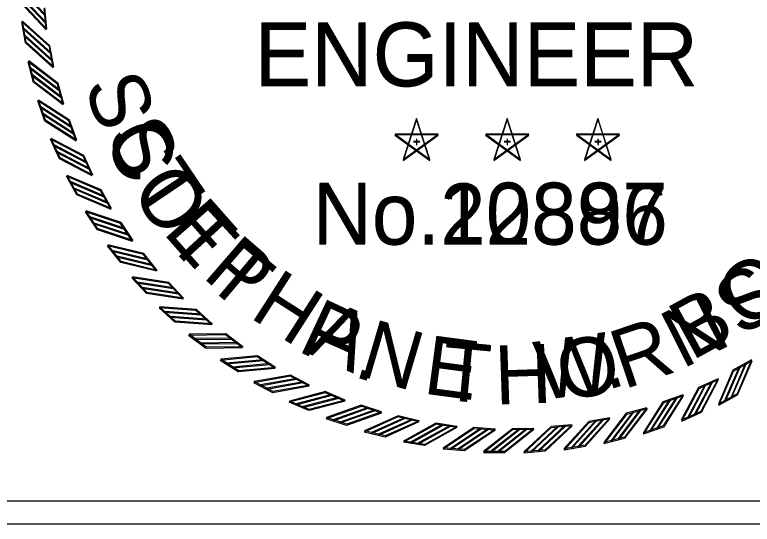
# Model space of a CAD drawing. Extents: x 0 to 1228740, y 0 to 152440.
# Drawn here: x 30.798 to 32.682, y 17.345 to 18.648 of the extents above; entities that cross this region are included whole.
import ezdxf

# ---------------------------------------------------------------- set-up
doc = ezdxf.new("R2010")
doc.units = 0
for name, color, linetype in [('R_No Plot', 7, 'Continuous'), ('STAMP', 7, 'Continuous'), ('STAMP_SWB', 7, 'Continuous')]:
    doc.layers.add(name, color=color, linetype=linetype)

msp = doc.modelspace()

# ---------------------------------------------------------------- linework, layer by layer
at = {"layer": 'R_No Plot'}
msp.add_lwpolyline([(30.6265, 20.205), (33.4865, 20.205), (33.4865, 17.3449), (30.6265, 17.3449)], close=True, dxfattribs=at)
msp.add_lwpolyline([(30.6265, 20.205), (33.4865, 20.205), (33.4865, 17.3449), (30.6265, 17.3449)], close=True, dxfattribs=at)
msp.add_lwpolyline([(30.6665, 20.1432), (30.6665, 17.4052), (33.4231, 17.4052)], dxfattribs=at)
msp.add_lwpolyline([(30.6665, 20.1432), (30.6665, 17.4052), (33.4231, 17.4052)], dxfattribs=at)
at = {"layer": 'STAMP'}
for p, q in [((30.8797, 18.6111), (30.8747, 18.6655)), ((30.8272, 18.5777), (30.8177, 18.6315)), ((30.8974, 18.5144), (30.8879, 18.5683)), ((30.8478, 18.4769), (30.8339, 18.5297)), ((30.923, 18.4196), (30.909, 18.4725)), ((30.8767, 18.3781), (30.8585, 18.4296)), ((30.9563, 18.3272), (30.9381, 18.3788)), ((31.8248, 18.3825), (31.7907, 18.2777)), ((31.8589, 18.2778), (31.8249, 18.3826)), ((32.0564, 18.3825), (32.0223, 18.2777)), ((32.0905, 18.2778), (32.0565, 18.3826)), ((32.288, 18.3825), (32.2539, 18.2777)), ((32.322, 18.2778), (32.2881, 18.3826)), ((31.8799, 18.3425), (31.7697, 18.3426)), ((31.7698, 18.3425), (31.8589, 18.2776)), ((31.7908, 18.2778), (31.88, 18.3425)), ((32.1115, 18.3425), (32.0013, 18.3426)), ((32.0014, 18.3425), (32.0905, 18.2776)), ((32.0224, 18.2778), (32.1116, 18.3425)), ((32.3431, 18.3425), (32.2329, 18.3426)), ((32.233, 18.3425), (32.3221, 18.2776)), ((32.254, 18.2778), (32.3432, 18.3425)), ((30.9136, 18.282), (30.8912, 18.3318)), ((31.817, 18.3249), (31.8334, 18.3249)), ((31.8249, 18.3308), (31.8249, 18.317)), ((32.0486, 18.3249), (32.065, 18.3249)), ((32.0565, 18.3308), (32.0565, 18.317)), ((32.2802, 18.3249), (32.2966, 18.3249)), ((32.2881, 18.3308), (32.2881, 18.317)), ((30.9972, 18.2379), (30.9747, 18.2878)), ((30.9583, 18.1893), (30.9319, 18.2371)), ((31.0452, 18.1523), (31.0188, 18.2001)), ((31.0106, 18.1006), (30.9803, 18.1461)), ((31.1002, 18.0709), (31.0699, 18.1164)), ((31.07, 18.0166), (31.036, 18.0594)), ((31.1618, 17.9943), (31.1278, 18.0372)), ((31.1361, 17.9377), (31.0987, 17.9775)), ((31.2294, 17.9231), (31.192, 17.963)), ((31.2085, 17.8646), (31.168, 17.9012)), ((31.3027, 17.8577), (31.2621, 17.8944)), ((31.2867, 17.7976), (31.2433, 17.8308)), ((31.3811, 17.7986), (31.3377, 17.8318)), ((31.4642, 17.7462), (31.4181, 17.7757)), ((31.3701, 17.7374), (31.3241, 17.7669)), ((32.6807, 17.7651), (32.6328, 17.7386)), ((31.5513, 17.7008), (31.5029, 17.7264)), ((32.595, 17.717), (32.5451, 17.6946)), ((31.4583, 17.6843), (31.41, 17.7098)), ((31.6419, 17.6627), (31.5915, 17.6842)), ((32.6436, 17.6782), (32.5958, 17.6518)), ((31.5505, 17.6386), (31.5003, 17.6601)), ((32.5057, 17.6762), (32.4541, 17.6579)), ((31.7352, 17.6323), (31.6833, 17.6496)), ((32.4133, 17.6429), (32.3604, 17.6289)), ((31.8308, 17.6097), (31.7776, 17.6226)), ((32.5509, 17.6335), (32.5011, 17.6111)), ((31.6462, 17.6007), (31.5944, 17.618)), ((31.9279, 17.595), (31.8739, 17.6035)), ((32.3185, 17.6173), (32.2646, 17.6078)), ((31.7447, 17.5708), (31.6916, 17.5837)), ((32.0259, 17.5884), (31.9714, 17.5924)), ((32.1241, 17.59), (32.0694, 17.5894)), ((32.2219, 17.5996), (32.1674, 17.5946)), ((32.4548, 17.5966), (32.4034, 17.5784)), ((32.3561, 17.5677), (32.3033, 17.5538)), ((31.8453, 17.5492), (31.7914, 17.5577)), ((32.2552, 17.5471), (32.2015, 17.5376)), ((31.9474, 17.5359), (31.8929, 17.54)), ((32.0502, 17.5312), (31.9956, 17.5307)), ((32.153, 17.5349), (32.0987, 17.5299))]:
    msp.add_line(p, q, dxfattribs=at)
for points in [[(30.8761, 18.6474), (30.8115, 18.7162)], [(30.8783, 18.6285), (30.8136, 18.6974)], [(30.8798, 18.611), (30.8151, 18.6798)], [(30.8878, 18.5683), (30.8177, 18.6315)], [(30.8908, 18.5503), (30.8207, 18.6136)], [(30.8945, 18.5317), (30.8244, 18.595)], [(30.8974, 18.5144), (30.8273, 18.5777)], [(30.909, 18.4725), (30.8339, 18.5297)], [(30.9135, 18.4548), (30.8384, 18.5121)], [(30.9187, 18.4366), (30.8436, 18.4939)], [(30.923, 18.4196), (30.8479, 18.4768)], [(30.938, 18.3787), (30.8584, 18.4296)], [(30.944, 18.3615), (30.8643, 18.4124)], [(30.9507, 18.3438), (30.8711, 18.3947)], [(30.9564, 18.3272), (30.8768, 18.378)], [(30.9747, 18.2877), (30.8912, 18.3319)], [(30.982, 18.2711), (30.8985, 18.3152)], [(30.9902, 18.254), (30.9066, 18.2981)], [(30.9972, 18.2379), (30.9137, 18.282)], [(31.0188, 18.2001), (30.9319, 18.2371)], [(31.0274, 18.1841), (30.9405, 18.2211)], [(31.037, 18.1677), (30.9501, 18.2047)], [(31.0453, 18.1522), (30.9584, 18.1893)], [(31.0699, 18.1163), (30.9802, 18.1461)], [(31.0798, 18.1011), (30.9902, 18.1309)], [(31.0907, 18.0856), (31.001, 18.1153)], [(31.1003, 18.0708), (31.0107, 18.1006)], [(31.1278, 18.0371), (31.036, 18.0594)], [(31.1389, 18.0228), (31.0471, 18.045)], [(31.1511, 18.0082), (31.0592, 18.0304)], [(31.1619, 17.9943), (31.07, 18.0166)], [(31.192, 17.9629), (31.0987, 17.9775)], [(31.2043, 17.9496), (31.111, 17.9642)], [(31.2176, 17.936), (31.1243, 17.9506)], [(31.2295, 17.9231), (31.1362, 17.9377)], [(31.2621, 17.8943), (31.1679, 17.9012)], [(31.2755, 17.882), (31.1813, 17.8889)], [(31.2899, 17.8696), (31.1956, 17.8764)], [(31.3028, 17.8577), (31.2086, 17.8645)], [(31.3377, 17.8317), (31.2432, 17.8308)], [(31.352, 17.8206), (31.2576, 17.8196)], [(31.3674, 17.8094), (31.2729, 17.8084)], [(31.3812, 17.7986), (31.2868, 17.7976)], [(31.4181, 17.7756), (31.3241, 17.7668)], [(31.4334, 17.7657), (31.3393, 17.7569)], [(31.4496, 17.7558), (31.3555, 17.747)], [(32.6653, 17.7568), (32.6282, 17.6699)], [(32.6807, 17.7652), (32.6437, 17.6783)], [(31.4643, 17.7462), (31.3702, 17.7374)], [(32.6329, 17.7386), (32.5958, 17.6517)], [(32.6489, 17.7473), (32.6118, 17.6604)], [(31.503, 17.7263), (31.41, 17.7098)], [(31.519, 17.7177), (31.4259, 17.7012)], [(32.5951, 17.7171), (32.551, 17.6336)], [(31.5359, 17.7091), (31.4429, 17.6927)], [(31.5514, 17.7008), (31.4584, 17.6843)], [(32.5619, 17.7019), (32.5177, 17.6184)], [(32.579, 17.7101), (32.5349, 17.6265)], [(31.5916, 17.6842), (31.5002, 17.6601)], [(32.5452, 17.6946), (32.5011, 17.6111)], [(31.6082, 17.6769), (31.5169, 17.6528)], [(31.6258, 17.6698), (31.5345, 17.6457)], [(31.6419, 17.6627), (31.5506, 17.6386)], [(32.4714, 17.6638), (32.4205, 17.5842)], [(32.4891, 17.6706), (32.4383, 17.5909)], [(32.5058, 17.6763), (32.4549, 17.5967)], [(31.6834, 17.6495), (31.5943, 17.6179)], [(31.7006, 17.6436), (31.6115, 17.612)], [(32.4134, 17.6429), (32.3561, 17.5678)], [(32.4542, 17.6579), (32.4033, 17.5783)], [(31.7187, 17.638), (31.6297, 17.6064)], [(31.7353, 17.6323), (31.6463, 17.6007)], [(31.7777, 17.6226), (31.6916, 17.5837)], [(32.3605, 17.6289), (32.3032, 17.5538)], [(32.3781, 17.6334), (32.3208, 17.5582)], [(32.3963, 17.6386), (32.3391, 17.5635)], [(31.7953, 17.6181), (31.7092, 17.5793)], [(31.8139, 17.614), (31.7277, 17.5752)], [(31.8309, 17.6097), (31.7448, 17.5709)], [(31.8739, 17.6035), (31.7913, 17.5577)], [(32.2647, 17.6077), (32.2014, 17.5376)], [(32.2826, 17.6107), (32.2194, 17.5406)], [(32.3012, 17.6144), (32.238, 17.5443)], [(32.3186, 17.6173), (32.2553, 17.5472)], [(31.8919, 17.6005), (31.8093, 17.5547)], [(31.9107, 17.5979), (31.8281, 17.5521)], [(31.928, 17.595), (31.8454, 17.5492)], [(31.9714, 17.5924), (31.8929, 17.5399)], [(31.9895, 17.5909), (31.911, 17.5384)], [(32.0085, 17.5899), (31.9299, 17.5374)], [(32.026, 17.5885), (31.9474, 17.536)], [(32.0695, 17.5894), (31.9955, 17.5306)], [(32.0877, 17.5894), (32.0137, 17.5306)], [(32.1066, 17.59), (32.0327, 17.5312)], [(32.1242, 17.59), (32.0503, 17.5312)], [(32.1675, 17.5945), (32.0986, 17.5298)], [(32.1856, 17.596), (32.1167, 17.5313)], [(32.2044, 17.5982), (32.1356, 17.5335)], [(32.222, 17.5996), (32.1531, 17.535)]]:
    msp.add_lwpolyline(points, dxfattribs=at)
at = {"layer": 'STAMP_SWB'}
for p, q in [((30.8781, 18.6093), (30.8731, 18.6639)), ((30.8256, 18.5759), (30.8161, 18.6298)), ((30.8958, 18.5126), (30.8863, 18.5665)), ((30.8462, 18.475), (30.8323, 18.5278)), ((30.9214, 18.4176), (30.9075, 18.4706)), ((30.8751, 18.3761), (30.8569, 18.4276)), ((30.9548, 18.3251), (30.9365, 18.3768)), ((31.8244, 18.3805), (31.7902, 18.2755)), ((31.8585, 18.2756), (31.8245, 18.3806)), ((32.0563, 18.3805), (32.0221, 18.2755)), ((32.0904, 18.2756), (32.0564, 18.3806)), ((32.2882, 18.3805), (32.254, 18.2755)), ((32.3223, 18.2756), (32.2883, 18.3806)), ((31.8796, 18.3404), (31.7692, 18.3405)), ((31.7693, 18.3404), (31.8585, 18.2755)), ((31.7904, 18.2756), (31.8797, 18.3404)), ((32.1115, 18.3404), (32.0011, 18.3405)), ((32.0012, 18.3404), (32.0904, 18.2755)), ((32.0223, 18.2756), (32.1116, 18.3404)), ((32.3434, 18.3404), (32.233, 18.3405)), ((32.2331, 18.3404), (32.3223, 18.2755)), ((32.2541, 18.2756), (32.3435, 18.3404)), ((30.9121, 18.2799), (30.8896, 18.3297)), ((31.8166, 18.3228), (31.833, 18.3228)), ((31.8245, 18.3287), (31.8245, 18.3148)), ((32.0485, 18.3228), (32.0649, 18.3228)), ((32.0564, 18.3287), (32.0564, 18.3148)), ((32.2804, 18.3228), (32.2968, 18.3228)), ((32.2883, 18.3287), (32.2883, 18.3148)), ((30.9957, 18.2357), (30.9732, 18.2857)), ((30.9568, 18.187), (30.9304, 18.2349)), ((31.0439, 18.1499), (31.0173, 18.1979)), ((31.0091, 18.0983), (30.9788, 18.1437)), ((31.0989, 18.0684), (31.0685, 18.114)), ((31.0686, 18.0141), (31.0346, 18.0569)), ((31.1605, 17.9918), (31.1265, 18.0347)), ((31.1348, 17.9351), (31.0974, 17.975)), ((31.2283, 17.9205), (31.1908, 17.9604)), ((31.2073, 17.8619), (31.1667, 17.8985)), ((31.3016, 17.855), (31.261, 17.8917)), ((31.2856, 17.7949), (31.2421, 17.828)), ((31.3802, 17.7958), (31.3366, 17.8291)), ((31.4634, 17.7433), (31.4172, 17.7729)), ((31.3692, 17.7345), (31.3231, 17.764)), ((32.6814, 17.7623), (32.6334, 17.7358)), ((31.5506, 17.6979), (31.5021, 17.7235)), ((31.4574, 17.6813), (31.4091, 17.7069)), ((32.5956, 17.7142), (32.5457, 17.6917)), ((31.6412, 17.6598), (31.5908, 17.6813)), ((32.5062, 17.6733), (32.4545, 17.655)), ((32.6443, 17.6753), (32.5964, 17.6488)), ((31.5498, 17.6356), (31.4995, 17.6571)), ((31.7347, 17.6293), (31.6827, 17.6466)), ((32.4137, 17.6399), (32.3607, 17.6259)), ((32.5515, 17.6305), (32.5016, 17.6081)), ((31.6456, 17.5977), (31.5937, 17.6149)), ((31.8304, 17.6066), (31.7772, 17.6196)), ((32.3188, 17.6142), (32.2648, 17.6047)), ((31.9277, 17.592), (31.8736, 17.6005)), ((32.0258, 17.5854), (31.9712, 17.5894)), ((32.1241, 17.5869), (32.0693, 17.5864)), ((32.222, 17.5965), (32.1674, 17.5915)), ((32.4553, 17.5935), (32.4037, 17.5753)), ((31.7442, 17.5678), (31.6911, 17.5807)), ((32.3564, 17.5646), (32.3035, 17.5507)), ((31.8449, 17.5461), (31.7909, 17.5546)), ((31.9471, 17.5328), (31.8926, 17.5368)), ((32.0501, 17.528), (31.9954, 17.5275)), ((32.1531, 17.5318), (32.0986, 17.5268)), ((32.2554, 17.544), (32.2015, 17.5345))]:
    msp.add_line(p, q, dxfattribs=at)
for points in [[(30.8745, 18.6457), (30.8098, 18.7146)], [(30.8767, 18.6268), (30.8119, 18.6957)], [(30.8782, 18.6092), (30.8134, 18.6782)], [(30.8863, 18.5665), (30.816, 18.6298)], [(30.8893, 18.5485), (30.819, 18.6119)], [(30.893, 18.5299), (30.8227, 18.5932)], [(30.8959, 18.5125), (30.8256, 18.5759)], [(30.9075, 18.4705), (30.8322, 18.5279)], [(30.9119, 18.4529), (30.8367, 18.5102)], [(30.9172, 18.4346), (30.8419, 18.492)], [(30.9215, 18.4176), (30.8463, 18.4749)], [(30.9365, 18.3767), (30.8568, 18.4276)], [(30.9424, 18.3595), (30.8627, 18.4104)], [(30.9492, 18.3417), (30.8694, 18.3926)], [(30.9549, 18.3251), (30.8752, 18.376)], [(30.9732, 18.2856), (30.8896, 18.3297)], [(30.9805, 18.2689), (30.8969, 18.3131)], [(30.9887, 18.2518), (30.9051, 18.2959)], [(30.9958, 18.2356), (30.9121, 18.2798)], [(31.0173, 18.1978), (30.9303, 18.2349)], [(31.026, 18.1818), (30.939, 18.2189)], [(31.0356, 18.1654), (30.9486, 18.2025)], [(31.0439, 18.1499), (30.9569, 18.187)], [(31.0685, 18.114), (30.9788, 18.1438)], [(31.0785, 18.0987), (30.9887, 18.1285)], [(31.0894, 18.0831), (30.9996, 18.1129)], [(31.099, 18.0684), (31.0092, 18.0982)], [(31.1265, 18.0346), (31.0346, 18.0569)], [(31.1377, 18.0203), (31.0457, 18.0426)], [(31.1498, 18.0056), (31.0579, 18.0279)], [(31.1606, 17.9918), (31.0687, 18.014)], [(31.1908, 17.9604), (31.0973, 17.975)], [(31.2031, 17.947), (31.1097, 17.9616)], [(31.2164, 17.9334), (31.123, 17.948)], [(31.2283, 17.9205), (31.1349, 17.9351)], [(31.261, 17.8917), (31.1667, 17.8985)], [(31.2744, 17.8793), (31.1801, 17.8862)], [(31.2888, 17.8669), (31.1944, 17.8738)], [(31.3017, 17.855), (31.2074, 17.8618)], [(31.3367, 17.829), (31.2421, 17.828)], [(31.351, 17.8178), (31.2565, 17.8168)], [(31.3664, 17.8066), (31.2718, 17.8057)], [(31.3803, 17.7958), (31.2857, 17.7948)], [(31.4172, 17.7728), (31.323, 17.764)], [(31.4325, 17.7628), (31.3383, 17.7541)], [(31.4487, 17.7529), (31.3545, 17.7442)], [(32.666, 17.754), (32.6288, 17.667)], [(32.6814, 17.7624), (32.6443, 17.6754)], [(31.4634, 17.7433), (31.3692, 17.7345)], [(32.6335, 17.7358), (32.5964, 17.6488)], [(32.6495, 17.7444), (32.6124, 17.6574)], [(31.5022, 17.7234), (31.409, 17.7069)], [(31.5182, 17.7148), (31.425, 17.6982)], [(31.5352, 17.7062), (31.442, 17.6897)], [(31.5506, 17.6979), (31.4575, 17.6814)], [(32.5624, 17.699), (32.5183, 17.6153)], [(32.5796, 17.7072), (32.5354, 17.6235)], [(32.5957, 17.7142), (32.5515, 17.6306)], [(31.5909, 17.6813), (31.4994, 17.6571)], [(32.5457, 17.6917), (32.5016, 17.608)], [(31.6076, 17.6739), (31.5161, 17.6498)], [(31.6252, 17.6669), (31.5337, 17.6427)], [(31.6413, 17.6598), (31.5499, 17.6356)], [(32.4718, 17.6609), (32.4209, 17.5812)], [(32.4896, 17.6676), (32.4387, 17.5879)], [(32.5063, 17.6733), (32.4553, 17.5936)], [(31.6828, 17.6465), (31.5936, 17.6149)], [(31.7, 17.6406), (31.6109, 17.609)], [(32.4138, 17.6399), (32.3564, 17.5647)], [(32.4546, 17.655), (32.4037, 17.5753)], [(31.7182, 17.635), (31.629, 17.6034)], [(31.7348, 17.6293), (31.6457, 17.5977)], [(32.3608, 17.6259), (32.3034, 17.5507)], [(32.3784, 17.6304), (32.3211, 17.5551)], [(32.3967, 17.6356), (32.3394, 17.5604)], [(31.7772, 17.6195), (31.691, 17.5807)], [(31.7949, 17.6151), (31.7087, 17.5762)], [(31.8135, 17.611), (31.7272, 17.5721)], [(31.8305, 17.6067), (31.7443, 17.5678)], [(32.2649, 17.6047), (32.2015, 17.5345)], [(32.2828, 17.6077), (32.2195, 17.5375)], [(32.3015, 17.6114), (32.2381, 17.5412)], [(32.3188, 17.6143), (32.2555, 17.5441)], [(31.8736, 17.6004), (31.7909, 17.5546)], [(31.8916, 17.5974), (31.8088, 17.5516)], [(31.9104, 17.5949), (31.8277, 17.549)], [(31.9278, 17.592), (31.845, 17.5461)], [(31.9712, 17.5893), (31.8926, 17.5368)], [(31.9894, 17.5878), (31.9107, 17.5353)], [(32.0083, 17.5869), (31.9297, 17.5343)], [(32.0259, 17.5854), (31.9472, 17.5329)], [(32.0694, 17.5864), (31.9954, 17.5275)], [(32.0876, 17.5864), (32.0136, 17.5275)], [(32.1066, 17.587), (32.0326, 17.5281)], [(32.1242, 17.587), (32.0502, 17.5281)], [(32.1675, 17.5915), (32.0986, 17.5267)], [(32.1857, 17.593), (32.1167, 17.5282)], [(32.2045, 17.5952), (32.1356, 17.5304)], [(32.2221, 17.5966), (32.1531, 17.5318)]]:
    msp.add_lwpolyline(points, dxfattribs=at)

# ---------------------------------------------------------------- texts
at = {"layer": 'STAMP'}
for s, height, p in [('ENGINEER', 0.16212, (31.4115, 18.4665)), ('No.10887', 0.15633, (31.5597, 18.0623))]:
    msp.add_text(s, height=height, dxfattribs=at).set_placement(p)
for s, rotation, p in [('S', 289.7007, (30.9736, 18.4683)), ('C', 296.9967, (31.0221, 18.3328)), ('O', 304.6575, (31.0911, 18.1984)), ('T', 312.6831, (31.1819, 18.0689)), ('T', 319.9791, (31.2795, 17.9631)), ('S', 35.4928, (32.6567, 17.8206)), ('N', 26.7376, (32.5035, 17.741)), ('P', 334.9359, (31.517, 17.7894)), ('R', 18.712, (32.354, 17.6893)), ('O', 10.6864, (32.1987, 17.6589)), ('T', 354.6351, (31.8831, 17.6643)), ('H', 1.9312, (32.0263, 17.6509)), ('.', 342.9615, (31.6608, 17.7233))]:
    msp.add_text(s, height=0.1509, rotation=rotation, dxfattribs=at).set_placement(p)
at = {"layer": 'STAMP_SWB'}
for s, height, rotation, p in [('ENGINEER', 0.16232, 360, (31.4106, 18.4646)), ('S', 0.1508, 296.6397, (31.0292, 18.339)), ('T', 0.1508, 304.0276, (31.0937, 18.2105)), ('No.22896', 0.15653, 360, (31.559, 18.0598)), ('E', 0.1508, 311.4154, (31.1742, 18.0913)), ('P', 0.1508, 319.1727, (31.2745, 17.9784)), ('O', 0.1508, 36.7453, (32.6658, 17.8388)), ('H', 0.1508, 327.2994, (31.3948, 17.8757)), ('B', 0.1508, 28.6187, (32.5275, 17.7621)), ('A', 0.1508, 336.1648, (31.5412, 17.7844)), ('N', 0.1508, 343.5527, (31.6728, 17.7263)), ('W', 0.1508, 7.9326, (32.1396, 17.6612)), ('E', 0.1508, 352.4181, (31.8389, 17.6796)), ('.', 0.1508, 16.7981, (32.3102, 17.6872))]:
    msp.add_text(s, height=height, rotation=rotation, dxfattribs=at).set_placement(p)

doc.saveas('drawing.dxf')
